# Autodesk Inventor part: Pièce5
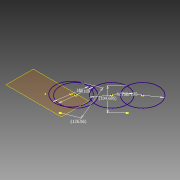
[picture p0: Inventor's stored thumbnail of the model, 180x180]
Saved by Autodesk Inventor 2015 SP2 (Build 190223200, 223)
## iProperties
Created: 2015-08
Part Number: Pièce5
Material: Générique
Document SubType Name: Modeling
Designer: Dominique
Density: 1 g/cm^3
Appearance: Par défaut
Author: Dominique
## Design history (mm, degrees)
node "Plan de construction1"
sketch "Esquisse1" dims "d0" = 100 (= d1), "d1" = 100, "d2" = 100 (= d1), "d3" = 100 (= d1)
  geometry: C1 r 3 at (-18.448, -0.357) reference; C2 r 3 at (197.56, 39.534) reference; C3 r 3 at (175.806, -34.459) reference; C4 r 3 at (28.3, -61.7) reference; 9 further points; 2 other entities
  constraints: 2 coincident, 14 other
  dimensions: "d4" = 104.68521 distance of point (9.289, 41.244) C4.centre (derived); "d5" = 104.68521 distance of point (156.795, 68.485) C3.centre (derived)
  node "Référence1"
  node "Référence2"
  node "Référence3"
  node "Référence4"
  node "Référence5"
  node "Référence6"
